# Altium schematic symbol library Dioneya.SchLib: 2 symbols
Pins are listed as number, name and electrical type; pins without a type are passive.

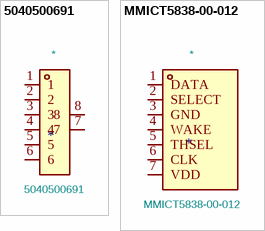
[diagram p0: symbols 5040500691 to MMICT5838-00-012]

## 5040500691
designator *  value 5040500691
Manufacturer: MOLEX; ki_keywords: Wire To Board / Wire To Wire Connector
footprint Molex_5040500691
pins: 1, 2, 3, 4, 5, 6, 7, 8

## MMICT5838-00-012
designator *  value MMICT5838-00-012
Manufacturer: TDK InvenSense(应美盛); ki_keywords: MEMS Microphones
footprint T5838_RevA
pins: 1 DATA, 2 SELECT, 3 GND, 4 WAKE, 5 THSEL, 6 CLK, 7 VDD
